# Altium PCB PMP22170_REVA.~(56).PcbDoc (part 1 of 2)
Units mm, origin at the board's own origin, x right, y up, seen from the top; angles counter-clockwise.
Board outline 78 x 48 mm, 2 copper layers (Top Layer, Bottom Layer), stack 1.575 mm thick; 75 components, 28 nets, 160 pads, 117 vias.
Unrouted connection lines stored in the file: 137.
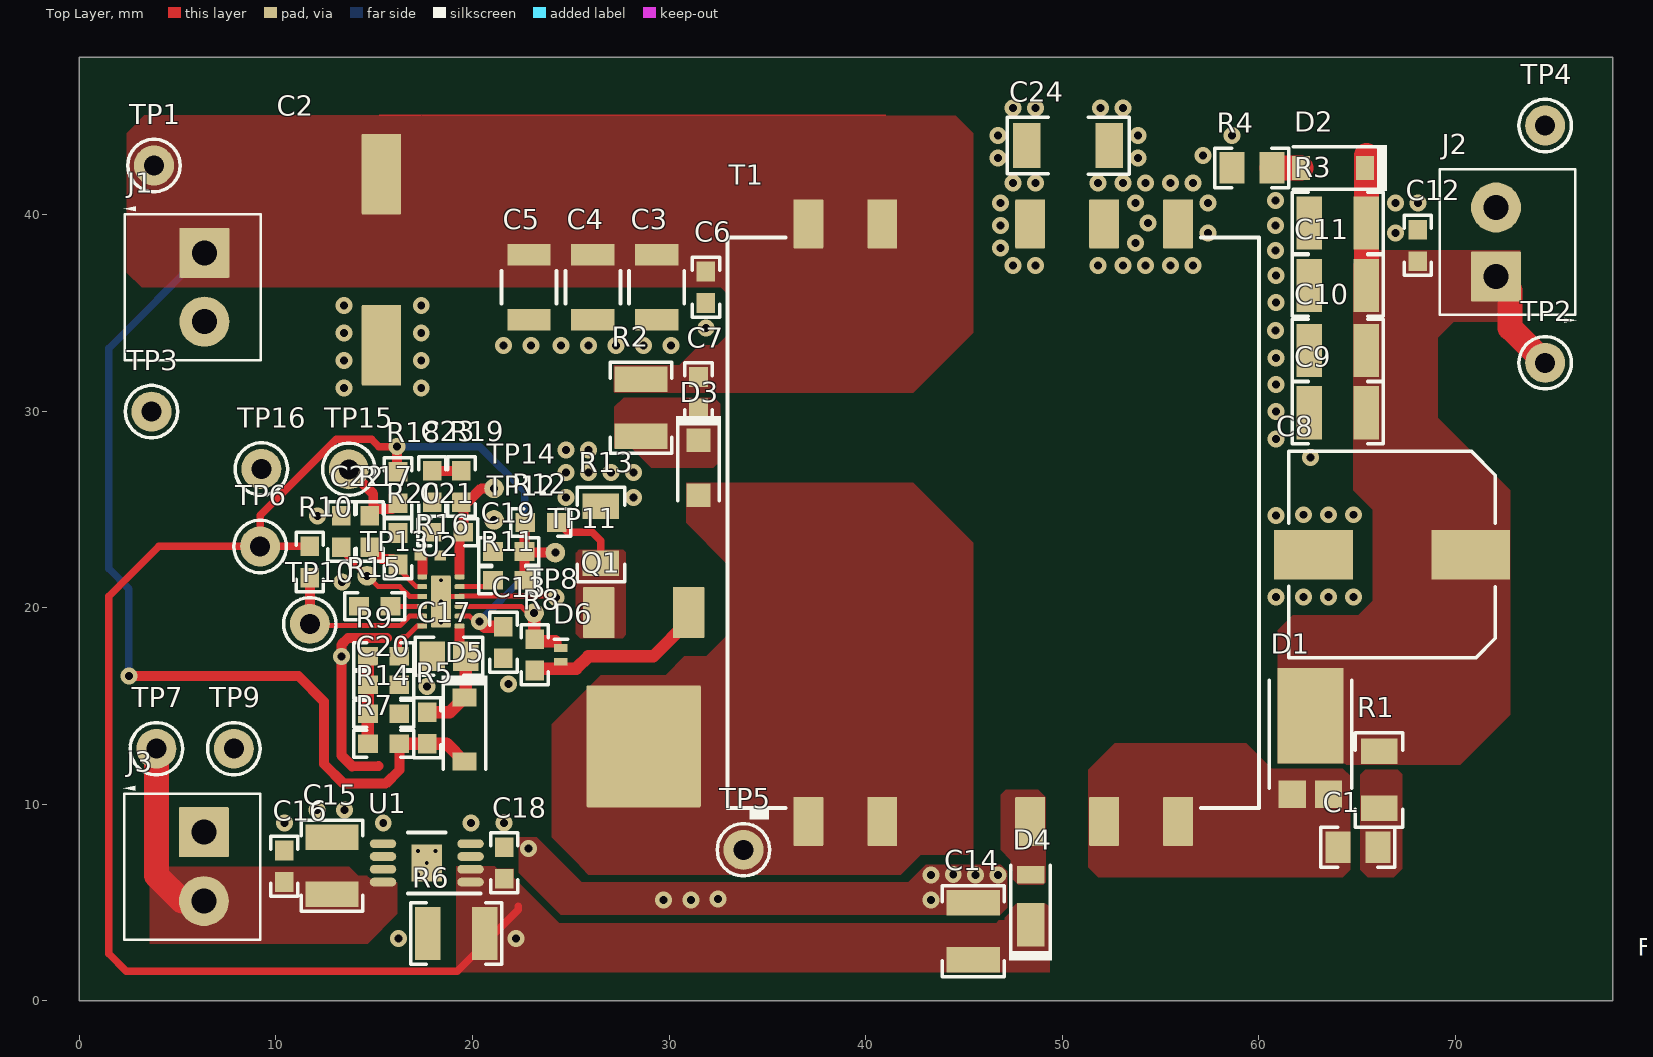
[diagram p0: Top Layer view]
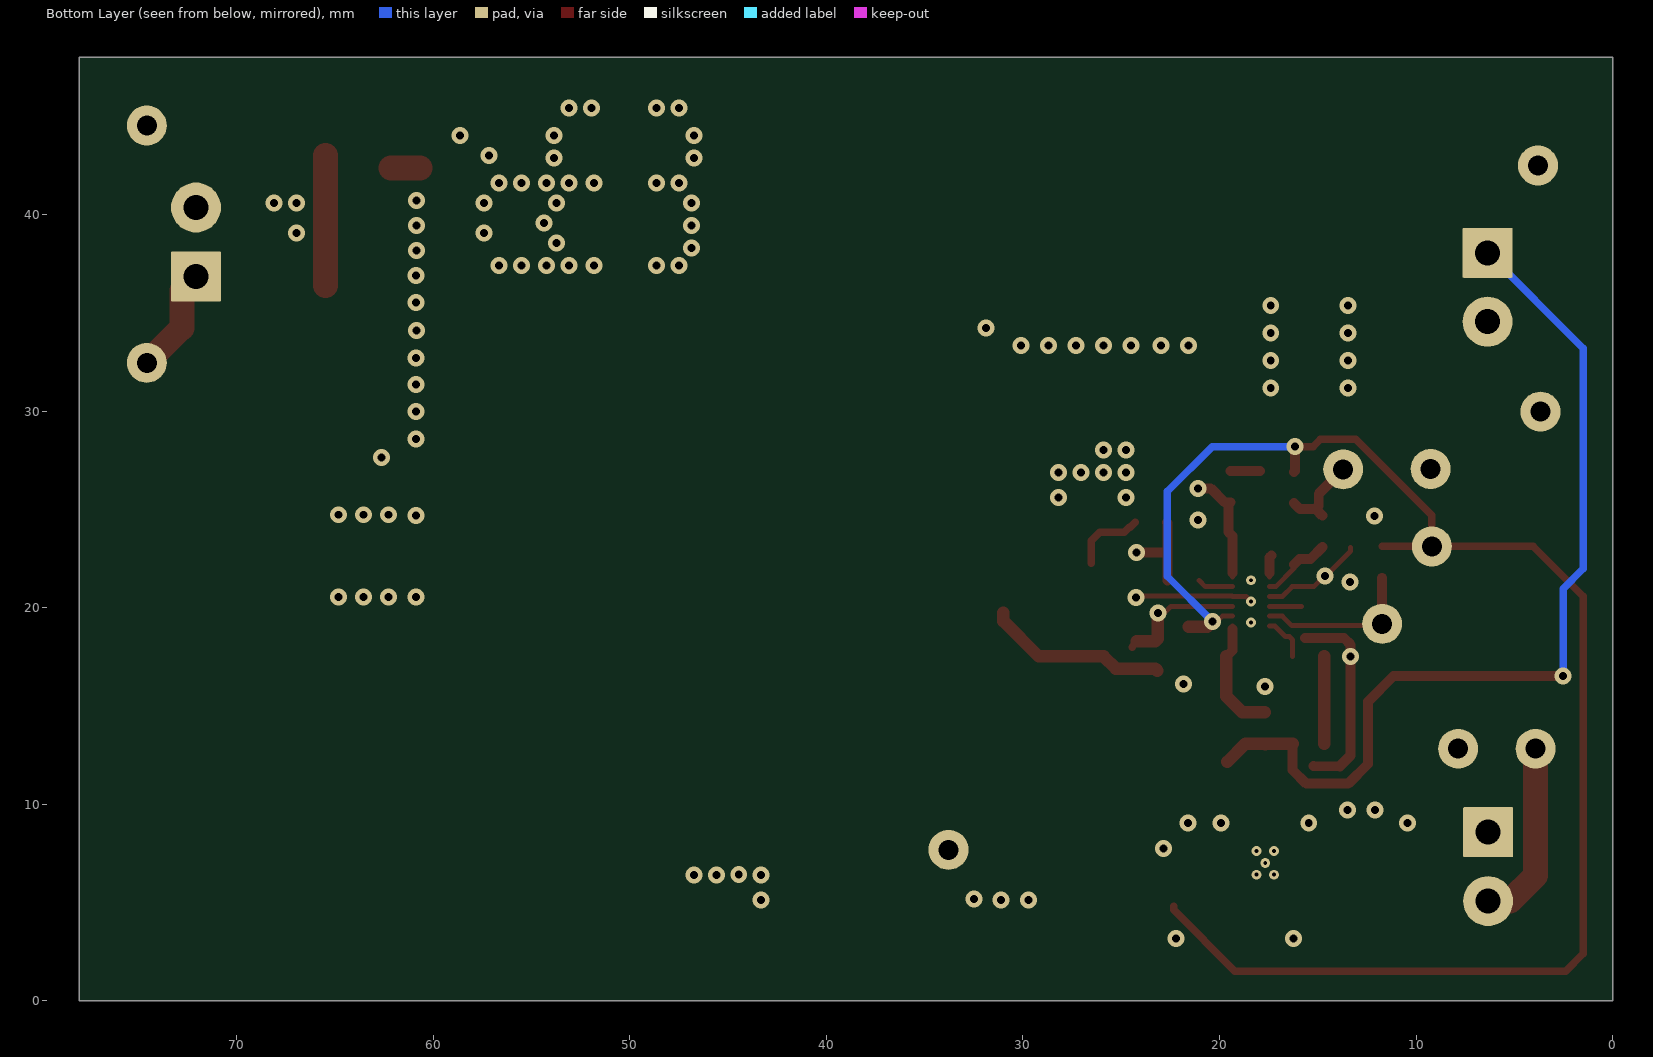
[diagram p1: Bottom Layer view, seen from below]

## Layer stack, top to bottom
Top Solder: solder mask 0.0102, Solder Resist, Dk 3.5
Top Layer: signal copper 0.0356
Dielectric1: core 1.5037, FR-4, Dk 4.8
Bottom Layer: signal copper 0.0356
Bottom Solder: solder mask 0.0102, Solder Resist, Dk 3.5

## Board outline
0,0 78,0 78,48 0,48

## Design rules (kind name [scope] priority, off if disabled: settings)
AcuteAngle [All] p1: minimum=4.50000000000000E+0001 checktracksonly=FALSE
AssemblyTestPointUsage [All] p1: valid=2
BoardOutlineClearance BoardOutlineClearance_MountingHoles [OnCopper and InComponentClass('Mounting Holes')] p1: gap=1 ignorepadtopadclearanceinfootprint=FALSE
BoardOutlineClearance BoardOutlineClearance_Poly [OnCopper and IsPoly] p2: gap=0.635 ignorepadtopadclearanceinfootprint=FALSE
BoardOutlineClearance [OnCopper and Not InComponentClass('Logo') and not InComponentClass('FiducialMark') and not InRegion(1000,500,4000,800) and not InPoly] p3: gap=1.27 ignorepadtopadclearanceinfootprint=FALSE
Clearance Clearance_Keepouts [((IsTrack Or IsArc) And Not InPoly) And IsFree and IsKeepOut vs ((IsTrack Or IsArc) And Not InPoly) And IsFree and IsKeepOut] p1: gap=0 ignorepadtopadclearanceinfootprint=FALSE
Clearance Clearance_Poly [InPolygon] p2: gap=0.254 ignorepadtopadclearanceinfootprint=TRUE
Clearance Clearance_FiducialMark [IsKeepOut and InComponentClass('FiducialMark') vs IsPad and InComponentClass('FiducialMark')] p3: gap=0 ignorepadtopadclearanceinfootprint=FALSE
Clearance [All] p4: gap=0.2 ignorepadtopadclearanceinfootprint=TRUE
ComponentClearance ComponentClearance_MountingHoles_FiducialMarks [InComponentClass('Mounting Holes') vs InComponentClass('FiducialMark')] p1: gap=1.27 collisioncheckmode=3 verticalgap=0.254 showdistances=FALSE
ComponentClearance ComponentClearance_Shunt [InComponentClass('Header') vs InComponentClass('Shunt')] p2: gap=0 collisioncheckmode=3 verticalgap=0 showdistances=FALSE
ComponentClearance ComponentClearance_Logo [InComponentClass('Logo')] p3: gap=1.27 collisioncheckmode=3 verticalgap=0.254 showdistances=FALSE
ComponentClearance ComponentClearance_ScrewToNut [(HasFootprint('NY PMS 440 0025 PH')) vs (HasFootprint('Keystone_1902C'))] p4: gap=0.127 collisioncheckmode=3 verticalgap=0.254 showdistances=FALSE
ComponentClearance ComponentClearance_MountingHoles [InComponentClass('Mounting Holes')] p5: gap=6.35 collisioncheckmode=3 verticalgap=2540 showdistances=FALSE
ComponentClearance ComponentClearance_SmallPassives [HasFootprint('0201*') or HasFootprint('0402*') or HasFootprint('0508') or HasFootprint('0603*') or HasFootprint('0612') or HasFootprint('0805*') or HasFootprint('0815*') or HasFootprint('0830*') or HasFootprint('1206*') or HasFootprint('1210*') or HasFootprint('1808*') or HasFootprint('1812*') or HasFootprint('1825*') or HasFootprint('2010*') or HasFootprint('2220*') or HasFootprint('2225*') or HasFootprint('2512*') or HasFootprint('2728*') or HasFootprint('3518*') vs HasFootprint('0201*') or HasFootprint('0402*') or HasFootprint('0508') or HasFootprint('0603*') or HasFootprint('0612') or HasFootprint('0805*') or HasFootprint('0815*') or HasFootprint('0830*') or HasFootprint('1206*') or HasFootprint('1210*') or HasFootprint('1808*') or HasFootprint('1812*') or HasFootprint('1825*') or HasFootprint('2010*') or HasFootprint('2220*') or HasFootprint('2225*') or HasFootprint('2512*') or HasFootprint('2728*') or HasFootprint('3518*')] p6: gap=0.38 collisioncheckmode=3 verticalgap=0.254 showdistances=FALSE
ComponentClearance ComponentClearance_THtoSMT [IsThruComponent vs IsSMTComponent] p7: gap=0.762 collisioncheckmode=3 verticalgap=0.762 showdistances=FALSE
ComponentClearance ComponentClearance_THtoTH [IsThruComponent vs IsThruComponent] p8: gap=0.762 collisioncheckmode=3 verticalgap=0.762 showdistances=FALSE
ComponentClearance [All] p9: gap=0.508 collisioncheckmode=3 verticalgap=0.254 showdistances=FALSE
DiffPairsRouting [All] p1: maxlimit=2.54 minlimit=0.254 mostfreqgap=0.254 toplayer_minwidth=0.381 toplayer_maxwidth=0.381 toplayer_prefwidth=0.381 bottomlayer_minwidth=0.381 bottomlayer_maxwidth=0.381 bottomlayer_prefwidth=0.381 maxuncoupledlength=25.4
FabricationTestPointUsage TestPointUsage [All] p1: valid=2 allowmultiple=FALSE
FabricationTestpoint Testpoint [All] p1: side=3 testpointundercomponent=TRUE minsize=1.016 maxsize=2.54 preferedsize=1.524 minholesize=0 maxholesize=1.016 preferedholesize=0.813 testpointgrid=0.025 allowsidetop=TRUE allowsidebottom=TRUE usegrid=TRUE gridtolerance=0
FanoutControl Fanout_LCC [IsLCC] p1: bgadir=Out bgaviamode=Centered fanoutstyle=Auto fanoutdirection=Alternating viagrid=0.025 // Fanout_LCC (Default Rule)
FanoutControl Fanout_BGA [IsBGA] p2: bgadir=Out bgaviamode=Centered fanoutstyle=Auto fanoutdirection=Alternating viagrid=0.025 // Fanout_BGA (Default Rule)
FanoutControl Fanout_Default [All] p4: bgadir=Out bgaviamode=Centered fanoutstyle=Auto fanoutdirection=Alternating viagrid=0.025 // Fanout_Default (Default Rule)
FanoutControl Fanout_Small [(CompPinCount < 5)] p5: bgadir=Out bgaviamode=Centered fanoutstyle=Auto fanoutdirection=OutThenIn viagrid=0.025 // Fanout_Small (Default Rule)
HoleSize [All] p1: absolutevalues=TRUE maxlimit=6.375 minlimit=0.2 maxpercent=80.000 minpercent=20.000
MinimumAnnularRing MinimumAnnularRing_ThermalPadVias [IsVia and InAnyComponent] p1: minimumring=0.15
MinimumAnnularRing [All] p2: minimumring=0.2
MinimumSolderMaskSliver MinimumSolderMaskSliver_Logo [InComponentClass('Logo') vs InComponentClass('Logo')] p1: minsoldermaskwidth=0.018
MinimumSolderMaskSliver [All] p2: minsoldermaskwidth=0.1
PlaneClearance [All] p1: clearance=0.381
PlaneConnect [All] p1: planeconnectstyle=Direct reliefexpansion=0.254 reliefentries=4 reliefconductorwidth=0.254 reliefairgap=0.254
PolygonConnect [All] p1: connectstyle=Direct reliefconductorwidth=0.254 reliefentries=4 polygonreliefangle="90 Angle" airgapwidth=0.254
RoutingVias ThermalPadVias [IsVia and InAnyComponent] p1: holewidth=0.2 width=0.5 viastyle="Through Hole" minholewidth=0.2 minwidth=0.5 maxholewidth=0.33 maxwidth=0.6
RoutingVias [All] p2: holewidth=0.406 width=0.864 viastyle="Through Hole" minholewidth=0.2 minwidth=0.66 maxholewidth=1.016 maxwidth=1.651
SilkToBoardRegionClearance [Not ((IsComment or IsDesignator) And (Hide <> 'False')) and not InRegion(1000,500,4000,800)] p1:
SilkToSilkClearance SilkToSilkClearance_Pb-FreeLogo [(HasFootprint('Pb-Free_Overlay_Medium') OR HasFootprint('Pb-Free_Overlay_Small')) vs (HasFootprint('Pb-Free_Overlay_Medium') OR HasFootprint('Pb-Free_Overlay_Small'))] p1: silktosilkclearance=0
SilkToSilkClearance [All] p2: silktosilkclearance=0
SilkToSolderMaskClearance SilkToComponentPadClearance [(IsPad or IsFill or IsRegion) and InAnycomponent] p1: minsilkscreentomaskgap=0.127 clearancetoexposedcopper=TRUE
SilkToSolderMaskClearance "Silk to Solder Mask Opening" [All] p2: minsilkscreentomaskgap=0 clearancetoexposedcopper=FALSE
SolderMaskExpansion [All] p1: expansion=0.05
UnRoutedNet [All] p1: checkbadconnections=TRUE
Width [All] p1: maxlimit=2.54 minlimit=0.152 preferedwidth=0.254 checkconnectedcopper=TRUE
13 further rules are at their usual default settings.

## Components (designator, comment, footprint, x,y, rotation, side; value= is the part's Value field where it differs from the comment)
C1 "Capacitor" 0805_HV 65.028,7.813 r180 top value=100pF
C2 "EEH-ZS1H221V" FP-EEHZS1H221P_RADIAL_SMD-MFG 15.377,37.692 r90 top
C3 "UMK325AB7106KMHT" 1210_280 29.377,36.295 r270 top value=10uF
C4 "UMK325AB7106KMHT" 1210_280 26.127,36.295 r270 top value=10uF
C5 "UMK325AB7106KMHT" 1210_280 22.877,36.295 r270 top value=10uF
C6 "Capacitor" 0603 31.877,36.295 r270 top value=0.1uF
C7 "Capacitor" 0603 31.5,30.927 r270 top value=0.1uF
C8 "EEHZC1E331P" SM_RADIAL_10BMM 66.768,22.693 r180 top value=330uF
C9 "TMK325B7226KMHT" 1210_270 64.012,29.911 r180 top value=22uF
C10 "TMK325B7226KMHT" 1210_270 64.012,33.086 r180 top value=22uF
C11 "TMK325B7226KMHT" 1210_270 64.012,36.388 r180 top value=22uF
C12 "Capacitor" 0603 68.076,38.42 r90 top value=0.1uF
C13 "GCM188R71E105KA64D" 0603 21.58,18.236 r270 top value=1uF
C14 "Capacitor" 1210_270 45.47,3.548 r90 top value=22uF
C15 "Capacitor" 1210_270 12.857,6.885 r90 top value=47uF
C16 "Capacitor" 0603 10.444,6.853 r90 top value=0.1uF
C17 "Capacitor" 0805 18.807,17.523 r180 top value=1uF
C18 "Capacitor" 0603 21.62,7.023 r90 top value=0.1uF
C19 "Capacitor" 0603 21.853,22.858 r180 top value=1000pF
C20 "Capacitor" 0603 15.492,16.076 r0 top value=10pF
C21 "CGA3E2X7R2A222K080AA" 0603 18.745,23.836 r180 top value=2200pF
C22 "Capacitor" 0603 13.336,23.871 r90 top value=0.1uF
C23 "CGA3E3X7R1H334K080AB" 0603 17.957,26.16 r270 top value=0.33uF
C24 "Capacitor" 1808 50.296,43.5 r180 top value=1000pF
D1 "PDS4200HQ-13" POWERDI5 62.615,12.512 r90 top value=200V
D2 "MMSZ5240B-7-F" SOD-123 63.762,42.357 r180 top value=10V
D3 "DIODE_SCHOTTKY" SOD-123W 31.5,27.117 r270 top value=100V
D4 "DFLS1200Q-7" PowerDI123 48.391,5.146 r90 top value=200V
D5 "SD103AW-7-F" SOD-123 19.608,13.803 r270 top value=40V
D6 "DIODE_SCHOTTKY" X1-DFN1006-2 24.499,17.601 r270 top value=30V
J1 "Receptacle_2x1" TERM_BLK_ED555-2DS 6.377,38.045 r270 top
J2 "Receptacle_2x1" TERM_BLK_ED555-2DS 72.051,36.842 r90 top
J3 "Receptacle_2x1" TERM_BLK_ED555-2DS 6.35,8.585 r270 top
Logo1 "FCC disclaimer" FCC_disclaimer 82.296,3.556 r0 top
Logo2 "WEEE logo" WEEE_Minimum 115.25,6.5 r0 top
Q1 "IPD60N10S4L12ATMA1" DPAK 28.715,16.35 r270 top value=100V
R1 "CRCW1206100RFKEAHP" 1206 66.108,11.242 r90 top value=100
R2 "ERJ14NF1001U" 1210 28.579,30.165 r90 top value=1.00k
R3 "ERJ14NF1001U" 1210 64.012,39.563 r0 top value=1.00k
R4 "CRCW080580R6FKEA" 0805_HV 59.637,42.357 r0 top value=80.6
R5 "Resistor" 0603 17.703,13.887 r270 top value=0
R6 "ERJ14NF1001U" 1210 19.177,3.429 r0 top value=1.00k
R7 "CRCW0603100KFKEA" 0603 15.492,13.078 r0 top value=100k
R8 "Resistor" 0603 23.172,17.601 r90 top value=10.0
R9 "CRCW060371K5FKEA" 0603 15.492,17.524 r0 top value=71.5k
R10 "CRCW060310K0FKEA" 0603 11.734,22.321 r270 top value=10.0k
R11 "Resistor" 0603 21.853,21.393 r0 top value=0
R12 "Resistor" 0603 23.485,24.332 r0 top value=100
R13 "ERJ-8BWFR010V" 1206 26.533,23.718 r270 top value=0.010
R14 "CRCW060324K9FKEA" 0603 15.492,14.603 r180 top value=24.9k
R15 "CRCW060373K2FKEA" 0603 15.036,20.068 r0 top value=73.2k
R16 "CRCW04020000Z0ED" 0402L 17.87,22.646 r180 top value=0
R17 "Resistor" 0603 14.782,23.874 r270 top value=6.04k
R18 "CRCW060320R0FKEA" 0603 16.217,26.111 r90 top value=20.0
R19 "CRCW06033K01FKEA" 0603 19.443,26.16 r270 top value=3.01k
R20 "CRCW06031K00FKEA" 0603 16.217,22.996 r270 top value=1.00k
T1 "750315862" Wurth_750315862 46.486,24.323 r90 top value=45uH
TP1 "5000" Keystone5000 3.814,42.484 r90 top
TP2 "5000" Keystone5000 74.553,32.451 r90 top
TP3 "5001" Keystone5001 3.687,29.97 r90 top
TP4 "5001" Keystone5001 74.551,44.516 r90 top
TP5 "5002" Keystone5002 33.786,7.686 r0 top
TP6 "5000" Keystone5000 9.207,23.111 r270 top
TP7 "5000" Keystone5000 3.937,12.827 r270 top
TP8 "TP_SM_1MM" TP_SM_1MM 23.142,19.723 r90 top
TP9 "5001" Keystone5001 7.874,12.827 r270 top
TP10 "5000" Keystone5000 11.734,19.175 r0 top
TP11 "TP_SM_1MM" TP_SM_1MM 24.217,22.796 r270 top
TP12 "TP_SM_1MM" TP_SM_1MM 21.105,24.459 r270 top
TP13 "TP_SM_1MM" TP_SM_1MM 14.655,21.621 r0 top
TP14 "TP_SM_1MM" TP_SM_1MM 21.105,26.068 r0 top
TP15 "5003" Keystone5003 13.717,27.035 r0 top
TP16 "5001" Keystone5001 9.275,27.051 r0 top
U1 "TPS7B8250QDGNRQ1" DGN0008D_N 17.683,7.023 r180 top
U2 "LM5155QDSSTQ1" DSS0012C 18.404,20.318 r180 top

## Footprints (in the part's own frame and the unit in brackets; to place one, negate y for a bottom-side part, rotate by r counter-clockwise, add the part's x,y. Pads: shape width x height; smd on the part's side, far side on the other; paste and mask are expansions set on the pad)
0402L [mm] "0402 from SM-752 data"
  rect 0.6x0.5 smd: 1(-0.5,0) 2(0.5,0)
  body extent -0.55,-0.3 0.55,0.3, height 0.6
0603 [mm] "0603 from SM-752 data"
  rect 1x0.95 smd: 1(-0.8,0) 2(0.8,0)
  silkscreen extent -1.52,-0.69 1.52,0.69, body extent -0.87,-0.47 0.87,0.47, height 1
0805 [mm] "0805 from SM-752 data"
  rect 1.3x1.5 smd: 1(-0.85,0) 2(0.85,0)
  silkscreen extent -1.72,-0.97 1.72,0.97, body extent -1.1,-0.72 1.1,0.72, height 1.45
0805_HV [mil] "0805 with 30mil clearance between pads"
  rect 50x63 smd: 1(-40,0) 2(40,0)
  silkscreen extent -74,-40 74,40, body extent -43,-29 43,29, height 57
1206 [mm] "1206 from SM-752 data"
  rect 1.3x1.85 smd: 1(-1.45,0) 2(1.45,0)
  silkscreen extent -2.4,-1.21 2.4,1.21, body extent -1.7,-0.9 1.7,0.9, height 1.35
1210 [mm] "1210 from SM-752 data"
  rect 1.3x2.7 smd: 1(-1.45,0) 2(1.45,0)
  silkscreen extent -2.32,-1.57 2.32,1.57, body extent -1.7,-1.35 1.7,1.35, height 1.35
1210_270 [mm] "1210"
  rect 1.3x2.7 smd: 1(-1.45,0) 2(1.45,0)
  silkscreen extent -2.32,-1.57 2.32,1.57, body extent -1.7,-1.35 1.7,1.35, height 2.7
1210_280 [mm] "SMD, 2-Leads, Body 3.6x2.8mm, Height 2.8mm"
  rect 1.1x2.2 smd: 1(-1.65,0) 2(1.65,0)
  silkscreen extent -0.84,-1.4 0.84,1.4, body extent -1.8,-1.4 1.8,1.4, height 2.8
1808 [mm] "Chip Capacitor, Body 4.6x2.0mm, IPC Medium Density"
  rect 1.4x2.3 smd: 1(-2.1,0) 2(2.1,0)
  silkscreen extent -3.1,-1.45 3.1,1.45, body extent -2.47,-1.2 2.47,1.2, height 2.03
DGN0008D_N [mm] "TSOP, 8-Leads, Body 3x3mm, Pitch 0.65mm, Thermal Pad 1.89x1.57mm, IPC Medium Density"
  rrect100% 1.35x0.45 smd: 1(-2.225,0.975) 2(-2.225,0.325) 3(-2.225,-0.325) 4(-2.225,-0.975) 5(2.225,-0.975) 6(2.225,-0.325) 7(2.225,0.325) 8(2.225,0.975)
  rrect6% 1.57x1.89 smd: 9(0,0)
  silkscreen extent -2.73,-1.55 0.95,1.55, body extent -2.46,-1.5 2.46,1.5, height 1.1
DPAK [mm] "D-PAK, 3-Pads, Body 6.22x6.73mm (max), TO-252AA using nominal STEP model"
  rrect6% 2.6x1.6 smd: 1(-3.4,2.28) 3(-3.4,-2.28)
  rrect2% 6.2x5.8 smd paste-3: 2(3.4,0)
  body extent -3.86,-3.29 5.84,3.29, height 2.48
DSS0012C [mm] "WSON-12"
  rrect40% 0.5x0.25 smd: 1(-0.95,1.25) 2(-0.95,0.75) 3(-0.95,0.25) 4(-0.95,-0.25) 5(-0.95,-0.75) 6(-0.95,-1.25) 7(0.95,-1.25) 8(0.95,-0.75) 9(0.95,-0.25) 10(0.95,0.25) 11(0.95,0.75) 12(0.95,1.25)
  rrect11% 0.95x1.17 on Top Paste: 13(0,0.685) 13(0,-0.685)
  rrect11% 1x2.65 smd paste-0.5: 13(0,0)
  body extent -1,-1.5 1,1.5, height 0.81
FCC_disclaimer [mm]
FP-EEHZS1H221P_RADIAL_SMD-MFG [mm]
  rrect5% 4.1x2 smd paste+0 mask+0: 1(-4.35,0) 2(4.35,0)
  body extent -6.65,-5.5 6.65,5.5, height 0.25
Keystone5000 [mil] "For Keystone 500x miniature loop terminals"
  round 80 hole 40: 1(0,0)
  silkscreen extent -52,-52 52,52, body extent -49,-49 49,49, height 182
Keystone5001 [mil] "For Keystone 500x miniature loop terminals"
  round 80 hole 40: 1(0,0)
  silkscreen extent -52,-52 52,52, body extent -49,-49 49,49, height 182
Keystone5002 [mil] "For Keystone 500x miniature loop terminals"
  round 80 hole 40: 1(0,0)
  silkscreen extent -52,-52 52,52, body extent -49,-49 49,49, height 182
Keystone5003 [mil] "For Keystone 500x miniature loop terminals"
  round 80 hole 40: 1(0,0)
  silkscreen extent -52,-52 52,52, body extent -49,-49 49,49, height 182
POWERDI5 [mm] "Diodes Inc recommended land pattern, ap02001.pdf rev 60"
  rect 1.4x1.39 smd: 1(-1.991,0.92) 2(-1.991,-0.92)
  rect 4.86x3.36 smd: 3(1.991,0)
  silkscreen extent -1.7,-2.1 3.8,2.1, body extent -2.27,-2.03 4.33,2.03, height 1.17
PowerDI123 [mm] "Diodes Inc recommended land pattern, document number DS30628 Rev. 6-2"
  rect 2.2x1.4 smd: 1(-1.275,0)
  rect 0.9x1.4 smd: 2(1.275,0)
  silkscreen extent -3.1,-1.09 1.76,1.09, body extent -2.38,-0.97 1.52,0.96, height 1
SM_RADIAL_10BMM [mm] "Nichicon 10x10"
  rect 4x2.5 smd: 1(-4,0) 2(4,0)
  silkscreen extent -5.25,-5.25 5.25,5.25, body extent -5.25,-5.25 5.25,5.25, height 10.5
SOD-123 [mm] "On Semi recommended land pattern"
  rect 0.915x1.22 smd: 1(-1.637,0) 2(1.637,0)
  silkscreen extent -2.74,-1.17 2.03,1.17, body extent -1.93,-0.9 1.93,0.9, height 1.35
SOD-123W [mm] "NXP recommended land pattern"
  rect 1.2x1.2 smd paste-0.05: 1(-1.4,0) 2(1.4,0)
  silkscreen extent -2.64,-1.14 1.68,1.14, body extent -1.85,-0.95 1.85,0.95, height 1.1
TERM_BLK_ED555-2DS [mil]
  rrect4% 100x100 hole 50: 1(0,0)
  round 100 hole 50: 2(138,0)
  silkscreen extent -93,-161 215,113, body extent -69,-150 207,106, height 323
TP_SM_1MM [mm] "1mm Test Point, SMT"
  round 1 smd paste-0.5: 1(0,0)
WEEE_Minimum [mm] "WEEElie bin"
  silkscreen extent -2.42,-4.38 2.52,2.65
Wurth_750315862 [mm] "SMD, 12-Leads, Body 32.45x27.03mm, Pitch 3.76mm"
  rrect7% 2.5x1.52 smd: 1(-15.19,9.4) 2(-15.19,5.64) 4(-15.19,-1.88) 5(-15.19,-5.64) 6(-15.19,-9.4) 7(15.19,-9.4) 8(15.19,-5.64) 9(15.19,-1.88) 11(15.19,5.64) 12(15.19,9.4)
  silkscreen extent -15.1,-13.51 14.5,13.51, body extent -16.25,-13.51 16.25,13.51, height 13.98
X1-DFN1006-2 [mm] "DIODES, INC"
  rect 0.4x0.7 smd: 1(-0.35,0) 2(0.35,0)
  silkscreen extent -0.8,-0.35 -0.8,0.35, body extent -0.54,-0.34 0.54,0.34, height 0.53

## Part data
C1: library part CMP-0008236-2, "CAP, CERM, 100 pF, 250 V, +/- 5%, C0G/NP0, 0805", Cap_Case=0805, Manufacturer=MuRata, PartNumber=GRM21A5C2E101JW01D, Supplier Part Number 1=490-5542-1-ND, TempCo=C0G/NP0, Tolerance_%=5%, Value1=Unknown, Value2=250V, ValueDisplayed=100pF
C2: library part CMP-0087071-1, "220µF 50V Aluminum Polymer Capacitor Radial, Can - SMD 13 mOhm 4000 Hrs @ 125°C", Manufacturer=Panasonic, Tolerance_%=20%
C3 C4 C5: library part CMP-0009258-2, "CAP, CERM, 10 uF, 50 V, +/- 10%, X7R, AEC-Q200 Grade 1, 1210", Cap_Case=1210, Manufacturer="Taiyo Yuden", Supplier Part Number 1=587-4326-1-ND, TempCo=X7R, Tolerance_%=10%, Value1=Unknown, Value2=50V, ValueDisplayed=10uF
C6 C7 C12: library part CMP-0007144-4, "CAP, CERM, 0.1 uF, 50 V, +/- 10%, X7R, 0603", Cap_Case=0603, Manufacturer=MuRata, PartNumber=GCM188R71H104KA57D, Supplier Part Number 1=490-4779-1-ND, TempCo=X7R, Tolerance_%=10%, Value1="0.02 ohm", Value2=50V, ValueDisplayed=0.1uF
C8: library part CMP-0012593-3, "CAP, Polymer Hybrid, 330 uF, 25 V, +/- 20%, 20 mohm, 10x10 SMD", Manufacturer=Panasonic, Supplier Part Number 1=P15459CT-ND, Tolerance_%=20%, Value1="20 ohm", Value2=25V, ValueDisplayed=330uF
C9 C10 C11: library part CMP-0009255-2, "CAP, CERM, 22 uF, 25 V, +/- 10%, X7R, AEC-Q200 Grade 1, 1210", Cap_Case=1210, Manufacturer="Taiyo Yuden", Supplier Part Number 1=587-4337-1-ND, TempCo=X7R, Tolerance_%=10%, Value1=Unknown, Value2=25V, ValueDisplayed=22uF
C13: library part CMP-0007139-4, "CAP, CERM, 1 uF, 25 V, +/- 10%, X7R, AEC-Q200 Grade 1, 0603", Cap_Case=0603, Manufacturer=MuRata, Supplier Part Number 1=490-10673-1-ND, TempCo=X7R, Tolerance_%=10%, Value1=Unknown, Value2=25V, ValueDisplayed=1uF
C14: library part CMP-0009224-2, "CAP, CERM, 22 uF, 25 V, +/- 10%, X7R, 1210", Cap_Case=1210, Manufacturer=MuRata, PartNumber=GRM32ER71E226KE15L, Supplier Part Number 1=490-5313-1-ND, TempCo=X7R, Tolerance_%=10%, Value1=Unknown, Value2=25V, ValueDisplayed=22uF
C15: library part CMP-0009220-2, "CAP, CERM, 47 uF, 10 V, +/- 10%, X7R, 1210", Cap_Case=1210, Manufacturer=MuRata, PartNumber=GRM32ER71A476KE15L, Supplier Part Number 1=490-5312-1-ND, TempCo=X7R, Tolerance_%=10%, Value1=Unknown, Value2=10V, ValueDisplayed=47uF
C16 C18 C22: library part CMP-0007378-5, "CAP, CERM, 0.1 uF, 16 V, +/- 10%, X7R, 0603", Cap_Case=0603, Manufacturer=MuRata, PartNumber=GRM188R71C104KA01D, Supplier Part Number 1=490-1532-1-ND, TempCo=X7R, Tolerance_%=10%, Value1=Unknown, Value2=16V, ValueDisplayed=0.1uF
C17: library part CMP-0008350-2, "CAP, CERM, 1 uF, 50 V, +/- 10%, X7R, 0805", Cap_Case=0805, Manufacturer=MuRata, PartNumber=GRM21BR71H105KA12L, Supplier Part Number 1=490-4736-1-ND, TempCo=X7R, Tolerance_%=10%, Value1=Unknown, Value2=50V, ValueDisplayed=1uF
C19: library part CMP-0007402-4, "CAP, CERM, 1000 pF, 25 V, +/- 10%, X7R, 0603", Cap_Case=0603, Manufacturer=MuRata, PartNumber=GRM188R71E102KA01D, Supplier Part Number 1=GRM188R71E102KA01D-ND, TempCo=X7R, Tolerance_%=10%, Value1=Unknown, Value2=25V, ValueDisplayed=1000pF
C20: library part CMP-0007170-4, "CAP, CERM, 10 pF, 50 V, +/- 5%, C0G/NP0, 0603", Cap_Case=0603, Manufacturer=MuRata, PartNumber=GRM1885C1H100JA01D, Supplier Part Number 1=490-1403-1-ND, TempCo=C0G/NP0, Tolerance_%=5%, Value1=Unknown, Value2=50V, ValueDisplayed=10pF
C21: library part CMP-0007085-4, "CAP, CERM, 2200 pF, 100 V, +/- 10%, X7R, AEC-Q200 Grade 1, 0603", Cap_Case=0603, Manufacturer=TDK, Supplier Part Number 1=445-5808-1-ND, TempCo=X7R, Tolerance_%=10%, Value1="0.923948 ohm", Value2=100V, ValueDisplayed=2200pF
C23: library part CMP-0007095-4, "CAP, CERM, 0.33 uF, 50 V, +/- 10%, X7R, AEC-Q200 Grade 1, 0603", Cap_Case=0603, Manufacturer=TDK, Supplier Part Number 1=445-174426-1-ND, TempCo=X7R, Tolerance_%=10%, Value1="0.01584 ohm", Value2=50V, ValueDisplayed=0.33uF
C24: library part CMP-0009436-2, "CAP, CERM, 1000 pF, 2000 V, +/- 10%, X7R, 1808", Cap_Case=1808, Manufacturer=MuRata, PartNumber=GR442QR73D102KW01L, Supplier Part Number 1=490-8145-1-ND, TempCo=X7R, Tolerance_%=10%, Value1=Unknown, Value2=2000V, ValueDisplayed=1000pF
D1: library part CMP-0081019-2, "Diode, Schottky, 200 V, 4 A, AEC-Q101, PowerDI5", Manufacturer="Diodes Inc.", Value1=4A, Value2=0.84V
D2: library part CMP-0005749-3, "Diode, Zener, 10 V, 500 mW, SOD-123", Manufacturer="Diodes Inc.", Power_W=500mW, Value1=0.5W
D3: library part CMP-0028782-2, "Diode, Schottky, 100 V, 1 A, AEC-Q101, SOD-123W", Manufacturer=Nexperia, PartNumber=PMEG10010ELRX, Value1=1A, Value2=0.77V
D4: library part CMP-0028517-2, "Diode, Schottky, 200 V, 1 A, PowerDI123", Manufacturer="Diodes Inc.", Value1=1A, Value2=0.85V
D5: library part CMP-0028543-1, "Diode, Schottky, 40 V, 0.35 A, SOD-123", Manufacturer="Diodes Inc.", Supplier Part Number 1=SD103-AWDICT-ND, Value1=0.35A, Value2=0.55V
D6: library part CMP-0076931-2, "Diode, Schottky, 30 V, 0.2 A, 1.00x0.50x0.60mm", Manufacturer="Diodes Inc.", PartNumber=BAT54LP-7, Value1=0.2A, Value2=1V
J1 J2 J3: library part CMP-0074913-1, "Terminal Block, 3.5mm Pitch, 2x1, TH", Color=Grey, Current_A=6A, Manufacturer="On-Shore Technology", PartNumber=ED555/2DS, Supplier Part Number 1=ED1514-ND, Voltage_V=150V
Logo1: library part CMP-0074847-1, "FCC_disclaimer"
Logo2: library part CMP-0074769-1
Q1: library part CMP-0080670-2, "MOSFET, N-CH, 100 V, 60 A, AEC-Q101, DPAK", Alternate Manufacturer=None, Manufacturer="Infineon Technologies", Supplier Part Number 1=IPD60N10S4L12ATMA1CT-ND, Value1="0.015 ohm", Value2="38 nC"
R1: library part CMP-0016570-3, "RES, 100, 1%, 0.5 W, AEC-Q200 Grade 0, 1206", Manufacturer=Vishay-Dale, Power_W=500mW, Supplier Part Number 1=541-100UCT-ND, TempCo="100 ppm/C", Tolerance_%=1%, Value2=0.5W, Value_Code=100R, ValueDisplayed=100
R2 R3 R6: library part CMP-0015030-3, "RES, 1.00 k, 1%, 0.5 W, AEC-Q200 Grade 0, 1210", Manufacturer=Panasonic, Power_W=500mW, Supplier Part Number 1=P1.00KAACT-ND, TempCo="100 ppm/C", Tolerance_%=1%, Value2=0.5W, Value_Code=1k00, ValueDisplayed=1.00k
R4: library part CMP-0021452-3, "RES, 80.6, 1%, 0.125 W, AEC-Q200 Grade 0, 0805", Manufacturer=Vishay-Dale, Power_W=125mW, Supplier Part Number 1=541-80.6CCT-ND, TempCo="100 ppm/C", Tolerance_%=1%, Value2=0.125W, Value_Code=80R6, ValueDisplayed=80.6
R5 R11: library part CMP-0025697-4, "RES, 0, 5%, 0.1 W, AEC-Q200 Grade 0, 0603", Manufacturer=Vishay-Dale, PartNumber=CRCW06030000Z0EA, Power_W=100mW, Supplier Part Number 1=541-0.0GCT-ND, TempCo="200 ppm/C", Tolerance_%=5%, Value2=0.1W, Value_Code=0000, ValueDisplayed=0
R7: library part CMP-0021990-4, "RES, 100 k, 1%, 0.1 W, AEC-Q200 Grade 0, 0603", Manufacturer=Vishay-Dale, Power_W=100mW, Supplier Part Number 1=541-100KHCT-ND, TempCo="100 ppm/C", Tolerance_%=1%, Value2=0.1W, Value_Code=100k
R8: library part CMP-0022003-4, "RES, 10.0, 1%, 0.1 W, AEC-Q200 Grade 0, 0603", Manufacturer=Vishay-Dale, PartNumber=CRCW060310R0FKEA, Power_W=100mW, Supplier Part Number 1=541-10.0HCT-ND, TempCo="100 ppm/C", Tolerance_%=1%, Value2=0.1W, Value_Code=10R0, ValueDisplayed=10.0
R9: library part CMP-0022581-4, "RES, 71.5 k, 1%, 0.1 W, AEC-Q200 Grade 0, 0603", Manufacturer=Vishay-Dale, Power_W=100mW, Supplier Part Number 1=541-71.5KHCT-ND, TempCo="100 ppm/C", Tolerance_%=1%, Value2=0.1W, Value_Code=71k5, ValueDisplayed=71.5k
R10: library part CMP-0021998-4, "RES, 10.0 k, 1%, 0.1 W, AEC-Q200 Grade 0, 0603", Manufacturer=Vishay-Dale, Power_W=100mW, Supplier Part Number 1=541-10.0KHCT-ND, TempCo="100 ppm/C", Tolerance_%=1%, Value2=0.1W, Value_Code=10k0, ValueDisplayed=10.0k
R12: library part CMP-0021991-4, "RES, 100, 1%, 0.1 W, AEC-Q200 Grade 0, 0603", Manufacturer=Vishay-Dale, PartNumber=CRCW0603100RFKEA, Power_W=100mW, Supplier Part Number 1=541-100HCT-ND, TempCo="100 ppm/C", Tolerance_%=1%, Value2=0.1W, Value_Code=100R, ValueDisplayed=100
R13: library part CMP-0750151-1, "RES, 0.010, 1%, 1 W, AEC-Q200 Grade 0, 1206", Manufacturer=Panasonic, Power_W=1W, TempCo="200 ppm/C", Tolerance_%=1%, Value_Code=R010, ValueDisplayed=0.010
R14: library part CMP-0022237-4, "RES, 24.9 k, 1%, 0.1 W, AEC-Q200 Grade 0, 0603", Manufacturer=Vishay-Dale, Power_W=100mW, Supplier Part Number 1=541-24.9KHCT-ND, TempCo="100 ppm/C", Tolerance_%=1%, Value2=0.1W, Value_Code=24k9, ValueDisplayed=24.9k
R15: library part CMP-0022585-4, "RES, 73.2 k, 1%, 0.1 W, AEC-Q200 Grade 0, 0603", Manufacturer=Vishay-Dale, Power_W=100mW, Supplier Part Number 1=541-73.2KHCT-ND, TempCo="100 ppm/C", Tolerance_%=1%, Value2=0.1W, Value_Code=73k2, ValueDisplayed=73.2k
R16: library part CMP-0026822-3, "RES, 0, 5%, 0.063 W, AEC-Q200 Grade 0, 0402", Manufacturer=Vishay-Dale, Power_W=63mW, Supplier Part Number 1=541-0.0JCT-ND, TempCo="200 ppm/C", Tolerance_%=5%, Value2=0.063W, Value_Code=0000, ValueDisplayed=0
R17: library part CMP-0022558-4, "RES, 6.04 k, 1%, 0.1 W, AEC-Q200 Grade 0, 0603", Manufacturer=Vishay-Dale, PartNumber=CRCW06036K04FKEA, Power_W=100mW, Supplier Part Number 1=541-6.04KHCT-ND, TempCo="100 ppm/C", Tolerance_%=1%, Value2=0.1W, Value_Code=6k04, ValueDisplayed=6.04k
R18: library part CMP-0022206-4, "RES, 20.0, 1%, 0.1 W, AEC-Q200 Grade 0, 0603", Manufacturer=Vishay-Dale, Power_W=100mW, Supplier Part Number 1=541-20.0HCT-ND, TempCo="100 ppm/C", Tolerance_%=1%, Value2=0.1W, Value_Code=20R0, ValueDisplayed=20.0
R19: library part CMP-0022371-4, "RES, 3.01 k, 1%, 0.1 W, AEC-Q200 Grade 0, 0603", Manufacturer=Vishay-Dale, Power_W=100mW, Supplier Part Number 1=541-3.01KHCT-ND, TempCo="100 ppm/C", Tolerance_%=1%, Value2=0.1W, Value_Code=3k01, ValueDisplayed=3.01k
R20: library part CMP-0022109-5, "RES, 1.00 k, 1%, 0.1 W, AEC-Q200 Grade 0, 0603", Manufacturer=Vishay-Dale, Power_W=100mW, Supplier Part Number 1=541-1.00KHCT-ND, TempCo="100 ppm/C", Tolerance_%=1%, Value2=0.1W, Value_Code=1k00, ValueDisplayed=1.00k
T1: library part CMP-0030646-1, "Transformer, 45 uH, SMT", Manufacturer="Wurth Elektronik", ValueDisplayed=45uH
TP1 TP2 TP6 TP7 TP10: library part CMP-0055137-1, "Test Point, Miniature, Red, TH", Color=Red, Manufacturer=Keystone, Supplier Part Number 1=36-5000-ND
TP3 TP4 TP9 TP16: library part CMP-0055138-1, "Test Point, Miniature, Black, TH", Color=Black, Manufacturer=Keystone, Supplier Part Number 1=36-5001-ND
TP5: library part CMP-0055139-1, "Test Point, Miniature, White, TH", Color=White, Manufacturer=Keystone, Supplier Part Number 1=36-5002-ND
TP8 TP11 TP12 TP13 TP14: library part CMP-0003825-1, "1mm Test Point, SMT", Manufacturer=Any
TP15: library part CMP-0055140-1, "Test Point, Miniature, Orange, TH", Color=Orange, Manufacturer=Keystone, Supplier Part Number 1=36-5003-ND
U1: library part CMP-0013313-4, "300mA High-Voltage Ultra-Low-Iq Low-Dropout (LDO) Regulator, DGN0008D (VSSOP-8)", Alternate Manufacturer="Texas Instruments"
U2: library part CMP-0081538-1, "Automotive Grade 2.2-MHz Wide Input Non-synchronous Boost Controller, DSS0012C (WSON-12)", Alternate Manufacturer="Texas Instruments", Alternate PartNumber=LM5155QDSSRQ1

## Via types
v1: diameter 0.864, hole 0.406, Top Layer to Bottom Layer, 109 vias
v2: diameter 0.5, hole 0.2, Top Layer to Bottom Layer, 8 vias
